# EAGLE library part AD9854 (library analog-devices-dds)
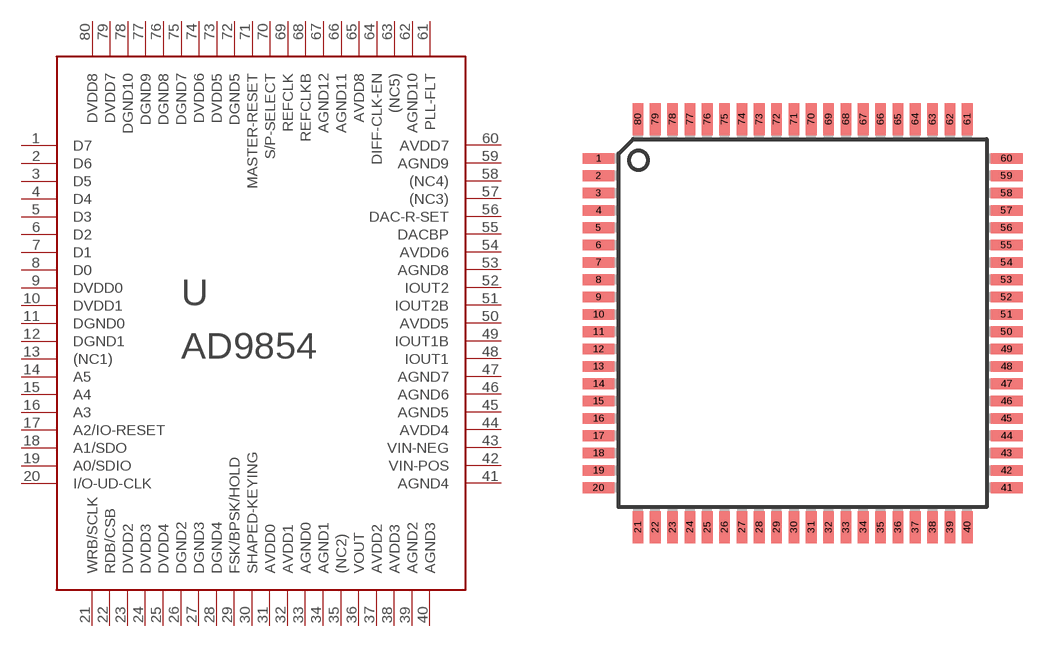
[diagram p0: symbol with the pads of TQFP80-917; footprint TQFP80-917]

Designator prefix -

## AD9854-(TQFP)  [TQFP80-917]
1  D7
2  D6
3  D5
4  D4
5  D3
6  D2
7  D1
8  D0
9  DVDD0
10  DVDD1
11  DGND0
12  DGND1
13  (NC1)
14  A5
15  A4
16  A3
17  A2/IO-RESET
18  A1/SDO
19  A0/SDIO
20  I/O-UD-CLK
21  WRB/SCLK
22  RDB/CSB
23  DVDD2
24  DVDD3
25  DVDD4
26  DGND2
27  DGND3
28  DGND4
29  FSK/BPSK/HOLD
30  SHAPED-KEYING
31  AVDD0
32  AVDD1
33  AGND0
34  AGND1
35  (NC2)
36  VOUT
37  AVDD2
38  AVDD3
39  AGND2
40  AGND3
41  AGND4
42  VIN-POS
43  VIN-NEG
44  AVDD4
45  AGND5
46  AGND6
47  AGND7
48  IOUT1
49  IOUT1B
50  AVDD5
51  IOUT2B
52  IOUT2
53  AGND8
54  AVDD6
55  DACBP
56  DAC-R-SET
57  (NC3)
58  (NC4)
59  AGND9
60  AVDD7
61  PLL-FLT
62  AGND10
63  (NC5)
64  DIFF-CLK-EN
65  AVDD8
66  AGND11
67  AGND12
68  REFCLKB
69  REFCLK
70  S/P-SELECT
71  MASTER-RESET
72  DGND5
73  DVDD5
74  DVDD6
75  DGND7
76  DGND8
77  DGND9
78  DGND10
79  DVDD7
80  DVDD8

## Footprint TQFP80-917 (pad centres in mm)
Thin Quad Flat Pack
smd 1.2 x 0.4: 1 -7.65,4.905; 2 -7.65,4.255; 3 -7.65,3.605; 4 -7.65,2.955; 5 -7.65,2.305; 6 -7.65,1.655; 7 -7.65,1.005; 8 -7.65,0.355; 9 -7.65,-0.295; 10 -7.65,-0.945; 11 -7.65,-1.595; 12 -7.65,-2.245; 13 -7.65,-2.895; 14 -7.65,-3.545; 15 -7.65,-4.195; 16 -7.65,-4.845; 17 -7.65,-5.495; 18 -7.65,-6.145; 19 -7.65,-6.795; 20 -7.65,-7.445; 41 7.65,-7.445; 42 7.65,-6.795; 43 7.65,-6.145; 44 7.65,-5.495; 45 7.65,-4.845; 46 7.65,-4.195; 47 7.65,-3.545; 48 7.65,-2.895; 49 7.65,-2.245; 50 7.65,-1.595; 51 7.65,-0.945; 52 7.65,-0.295; 53 7.65,0.355; 54 7.65,1.005; 55 7.65,1.655; 56 7.65,2.305; 57 7.65,2.955; 58 7.65,3.605; 59 7.65,4.255; 60 7.65,4.905
smd 0.4 x 1.2: 21 -6.175,-8.92; 22 -5.525,-8.92; 23 -4.875,-8.92; 24 -4.225,-8.92; 25 -3.575,-8.92; 26 -2.925,-8.92; 27 -2.275,-8.92; 28 -1.625,-8.92; 29 -0.975,-8.92; 30 -0.325,-8.92; 31 0.325,-8.92; 32 0.975,-8.92; 33 1.625,-8.92; 34 2.275,-8.92; 35 2.925,-8.92; 36 3.575,-8.92; 37 4.225,-8.92; 38 4.875,-8.92; 39 5.525,-8.92; 40 6.175,-8.92; 61 6.175,6.38; 62 5.525,6.38; 63 4.875,6.38; 64 4.225,6.38; 65 3.575,6.38; 66 2.925,6.38; 67 2.275,6.38; 68 1.625,6.38; 69 0.975,6.38; 70 0.325,6.38; 71 -0.325,6.38; 72 -0.975,6.38; 73 -1.625,6.38; 74 -2.275,6.38; 75 -2.925,6.38; 76 -3.575,6.38; 77 -4.225,6.38; 78 -4.875,6.38; 79 -5.525,6.38; 80 -6.175,6.38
